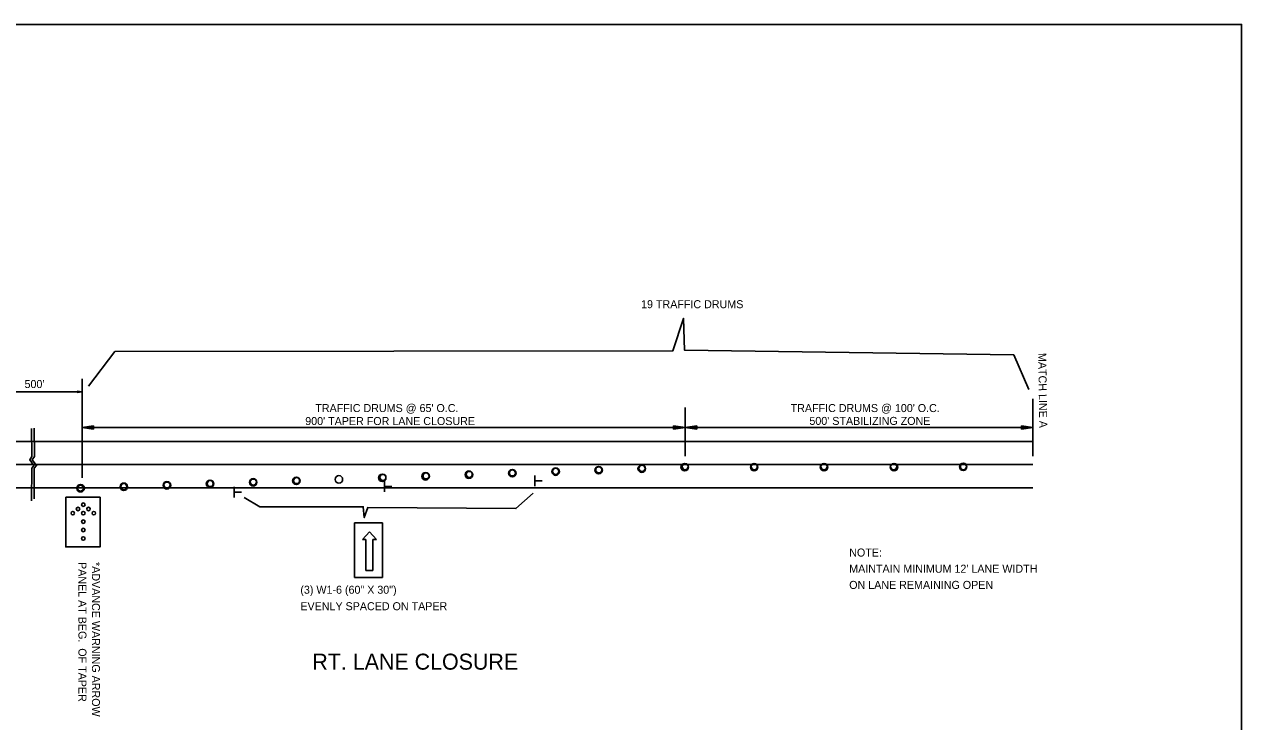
# Model space of a CAD drawing. Extents: x 1374027 to 1374537, y 380415 to 381405.
# Drawn here: x 1374105.8 to 1374197.1, y 380912.9 to 380965.2 of the extents above; entities that cross this region are included whole.
import ezdxf

# ---------------------------------------------------------------- set-up
doc = ezdxf.new("R2010")
doc.units = 0
doc.layers.add('Default', color=7, linetype='Continuous')
doc.layers.add('DSN_DRFT_Junk-No-Plot', color=7, linetype='Continuous')

msp = doc.modelspace()

# ---------------------------------------------------------------- linework, layer by layer
at = {"layer": 'Default'}
for p, q in [((1374110.164, 380938.607), (1374110.164, 380931.193)), ((1374103.617, 380937.627), (1374110.164, 380937.627)), ((1374109.789, 380937.684), (1374110.164, 380937.627)), ((1374109.789, 380937.684), (1374109.789, 380937.571)), ((1374109.789, 380937.674), (1374110.101, 380937.627)), ((1374109.789, 380937.665), (1374110.037, 380937.627)), ((1374109.789, 380937.655), (1374109.974, 380937.627)), ((1374109.789, 380937.646), (1374109.911, 380937.627)), ((1374109.789, 380937.636), (1374109.848, 380937.627)), ((1374109.789, 380937.571), (1374110.164, 380937.627)), ((1374109.789, 380937.609), (1374109.911, 380937.627)), ((1374109.789, 380937.59), (1374110.037, 380937.627)), ((1374109.789, 380937.581), (1374110.101, 380937.627)), ((1374109.789, 380937.6), (1374109.974, 380937.627)), ((1374109.789, 380937.619), (1374109.848, 380937.627)), ((1374181.443, 380937.109), (1374181.443, 380932.803)), ((1374110.164, 380936.324), (1374110.164, 380932.803)), ((1374155.365, 380936.46), (1374155.365, 380932.803)), ((1374110.164, 380934.956), (1374111.033, 380935.086)), ((1374155.365, 380934.956), (1374110.164, 380934.956)), ((1374111.033, 380934.825), (1374110.164, 380934.956)), ((1374111.033, 380935.086), (1374111.033, 380934.825)), ((1374154.496, 380934.825), (1374154.496, 380935.086)), ((1374154.496, 380935.086), (1374155.365, 380934.956)), ((1374155.365, 380934.956), (1374154.496, 380934.825)), ((1374155.365, 380934.956), (1374156.234, 380935.086)), ((1374181.443, 380934.956), (1374155.365, 380934.956)), ((1374156.234, 380934.825), (1374155.365, 380934.956)), ((1374156.234, 380935.086), (1374156.234, 380934.825)), ((1374180.573, 380934.825), (1374180.573, 380935.086)), ((1374180.573, 380935.086), (1374181.443, 380934.956)), ((1374181.443, 380934.956), (1374180.573, 380934.825)), ((1374039.716, 380933.916), (1374181.443, 380933.916)), ((1374039.716, 380932.177), (1374181.443, 380932.177)), ((1374144.108, 380930.569), (1374144.108, 380931.352)), ((1374039.716, 380930.439), (1374181.443, 380930.439)), ((1374121.567, 380929.717), (1374121.567, 380930.499)), ((1374132.838, 380930.143), (1374132.838, 380930.925)), ((1374132.849, 380930.532), (1374133.383, 380930.532)), ((1374144.12, 380930.959), (1374144.654, 380930.959)), ((1374121.578, 380930.106), (1374122.112, 380930.106)), ((1374131.184, 380926.568), (1374131.703, 380927.138)), ((1374131.703, 380927.138), (1374132.222, 380926.568)), ((1374131.444, 380926.568), (1374131.184, 380926.568)), ((1374131.444, 380924.238), (1374131.444, 380926.568)), ((1374131.963, 380924.238), (1374131.963, 380926.568)), ((1374131.963, 380926.568), (1374132.222, 380926.568)), ((1374131.444, 380924.238), (1374131.963, 380924.238))]:
    msp.add_line(p, q, dxfattribs=at)
for points in [[(1374110.65, 380938.041), (1374112.626, 380940.658), (1374154.452, 380940.706), (1374155.258, 380943.125), (1374155.33, 380940.741), (1374179.999, 380940.408), (1374181.14, 380937.81)], [(1374106.566, 380934.905), (1374106.599, 380932.775), (1374106.436, 380932.533), (1374106.753, 380932.1), (1374106.586, 380931.9), (1374106.586, 380929.604)], [(1374106.367, 380934.886), (1374106.399, 380932.783), (1374106.237, 380932.541), (1374106.553, 380932.109), (1374106.387, 380931.909), (1374106.386, 380929.463)], [(1374122.319, 380929.696), (1374123.477, 380929.014), (1374131.242, 380929.014), (1374131.311, 380928.196), (1374131.583, 380928.946), (1374142.686, 380928.878), (1374143.98, 380930.037)]]:
    msp.add_lwpolyline(points, dxfattribs=at)
for points in [[(1374108.939, 380929.725), (1374108.939, 380926.001), (1374111.515, 380926.001), (1374111.515, 380929.725)], [(1374130.59, 380927.803), (1374130.59, 380923.717), (1374132.68, 380923.717), (1374132.68, 380927.803)]]:
    msp.add_lwpolyline(points, close=True, dxfattribs=at)
for centre, radius in [((1374155.337, 380931.98), 0.281), ((1374155.359, 380932.013), 0.229), ((1374155.372, 380932.012), 0.229), ((1374160.541, 380931.98), 0.281), ((1374160.549, 380932.01), 0.229), ((1374165.783, 380931.98), 0.281), ((1374165.776, 380932.01), 0.229), ((1374171.026, 380931.98), 0.281), ((1374171.003, 380932.01), 0.229), ((1374176.212, 380932.007), 0.281), ((1374176.23, 380932.01), 0.229), ((1374129.415, 380931.066), 0.281), ((1374132.665, 380931.183), 0.281), ((1374132.714, 380931.209), 0.229), ((1374135.915, 380931.299), 0.281), ((1374135.951, 380931.324), 0.229), ((1374139.165, 380931.416), 0.281), ((1374139.188, 380931.438), 0.229), ((1374142.415, 380931.532), 0.281), ((1374142.425, 380931.553), 0.229), ((1374145.665, 380931.648), 0.281), ((1374145.661, 380931.668), 0.229), ((1374148.886, 380931.758), 0.281), ((1374148.898, 380931.782), 0.229), ((1374152.112, 380931.869), 0.281), ((1374152.135, 380931.897), 0.229), ((1374110.058, 380930.402), 0.281), ((1374110.044, 380930.407), 0.229), ((1374110.057, 380930.406), 0.229), ((1374113.292, 380930.513), 0.281), ((1374113.294, 380930.521), 0.229), ((1374116.525, 380930.624), 0.281), ((1374116.53, 380930.636), 0.229), ((1374119.759, 380930.735), 0.281), ((1374119.767, 380930.75), 0.229), ((1374122.992, 380930.845), 0.281), ((1374123.004, 380930.865), 0.229), ((1374126.226, 380930.956), 0.281), ((1374126.241, 380930.98), 0.229), ((1374109.467, 380928.534), 0.131), ((1374109.861, 380928.85), 0.131), ((1374110.256, 380929.167), 0.131), ((1374110.256, 380928.534), 0.131), ((1374110.651, 380928.85), 0.131), ((1374111.045, 380928.534), 0.131), ((1374110.256, 380927.902), 0.131), ((1374110.256, 380927.269), 0.131), ((1374110.256, 380926.637), 0.131)]:
    msp.add_circle(centre, radius, dxfattribs=at)
at = {"layer": 'DSN_DRFT_Junk-No-Plot'}
for points in [[(1374027.083, 380965.174), (1374197.083, 380965.174), (1374197.083, 380855.174), (1374027.083, 380855.174)], [(1374027.083, 380965.174), (1374027.083, 380855.174), (1374197.083, 380855.174), (1374197.083, 380965.174)]]:
    msp.add_lwpolyline(points, close=True, dxfattribs=at)

# ---------------------------------------------------------------- texts
at = {"layer": 'Default'}
for s, height, p in [('19 TRAFFIC DRUMS', 0.6, (1374152.066, 380943.897)), ("500'", 0.6, (1374105.85, 380937.913)), ("TRAFFIC DRUMS @ 65' O.C.", 0.6, (1374127.648, 380936.112)), ("TRAFFIC DRUMS @ 100' O.C.", 0.6, (1374163.279, 380936.112)), ("900' TAPER FOR LANE CLOSURE", 0.6, (1374126.892, 380935.138)), ("500' STABILIZING ZONE", 0.6, (1374164.683, 380935.148)), ('NOTE:', 0.6, (1374167.667, 380925.282)), ("MAINTAIN MINIMUM 12' LANE WIDTH", 0.6, (1374167.667, 380924.069)), ('ON LANE REMAINING OPEN', 0.6, (1374167.667, 380922.856)), ('RT. LANE CLOSURE', 1.2, (1374127.425, 380916.803))]:
    msp.add_text(s, height=height, dxfattribs=at).set_placement(p)
for s, rotation, p in [('MATCH LINE A', 270.80593, (1374181.835, 380940.537)), ('*ADVANCE WARNING ARROW', 270, (1374110.905, 380924.87)), ('PANEL AT BEG.  OF TAPER', 270, (1374109.892, 380924.87)), ('(3) W1-6 (60" X 30")', 0.00754, (1374126.527, 380922.493)), ('EVENLY SPACED ON TAPER', 0.00754, (1374126.527, 380921.258))]:
    msp.add_text(s, height=0.6, rotation=rotation, dxfattribs=at).set_placement(p)

doc.saveas('drawing.dxf')
